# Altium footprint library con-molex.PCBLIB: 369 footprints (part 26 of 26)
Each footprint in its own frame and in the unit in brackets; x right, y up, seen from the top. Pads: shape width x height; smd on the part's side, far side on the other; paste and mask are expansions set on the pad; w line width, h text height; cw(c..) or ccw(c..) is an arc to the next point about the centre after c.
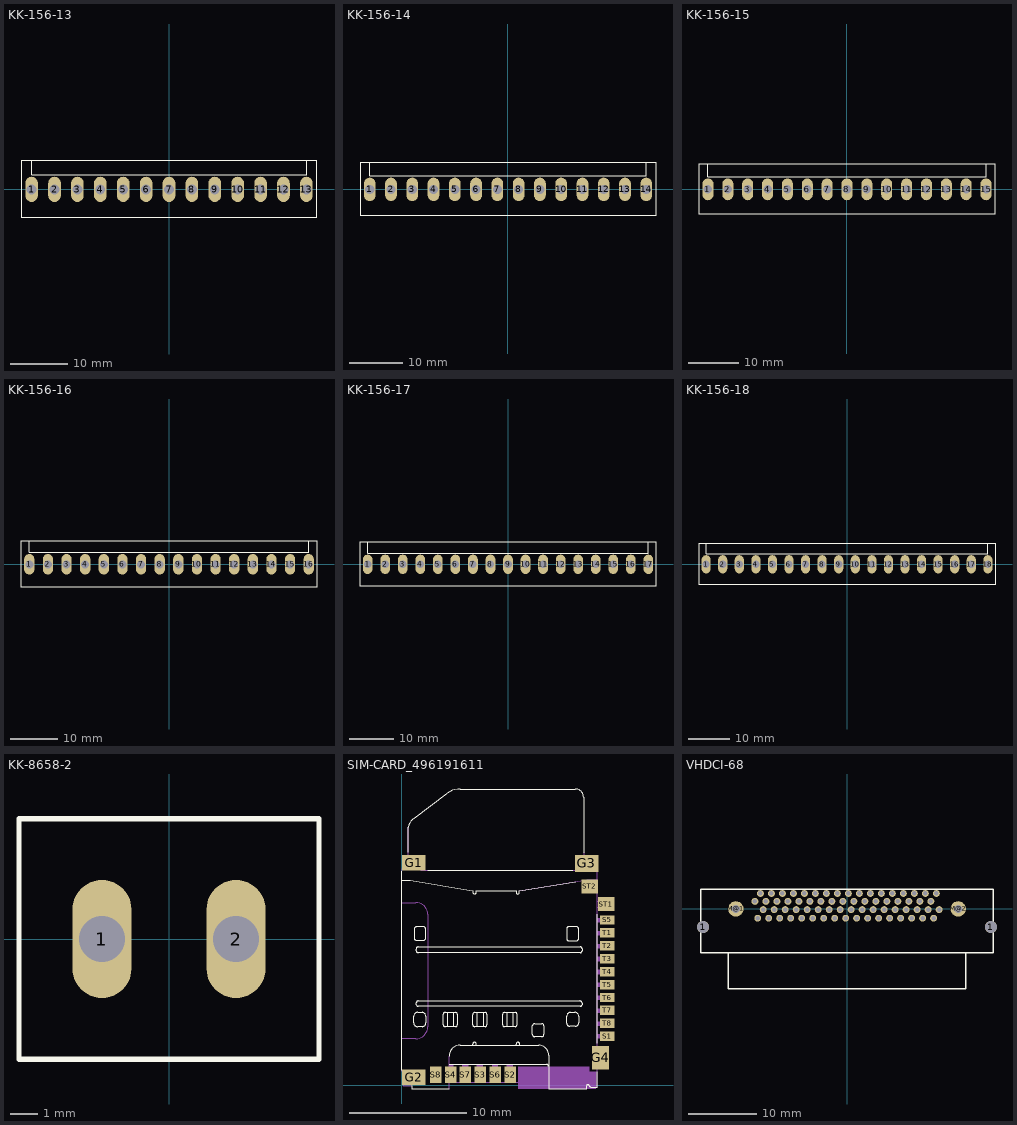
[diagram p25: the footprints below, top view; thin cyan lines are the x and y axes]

## KK-156-13 [mil]
pads (13):
  oval 86x172 hole 66.93: 1(-935.43,0) 2(-779.53,0) 3(-623.62,0) 4(-467.72,0) 5(-311.81,0) 6(-155.91,0) 7(0,0) 8(155.91,0) 9(311.81,0) 10(467.72,0) 11(623.62,0) 12(779.53,0) 13(935.43,0)
Top Overlay:
  lines w8: -935.63,194.88 936.61,194.88 ; -935.63,194.88 -1006.5,194.88 -1006.5,-189.96 1007.48,-189.96 1007.48,194.88 936.61,194.88 ; -935.63,194.88 -935.63,99.41 936.61,99.41 936.61,194.88

## KK-156-14 [mil]
pads (14):
  oval 86x172 hole 66.93: 1(-1013.39,0) 2(-857.48,0) 3(-701.57,0) 4(-545.67,0) 5(-389.76,0) 6(-233.86,0) 7(-77.95,0) 8(77.95,0) 9(233.86,0) 10(389.76,0) 11(545.67,0) 12(701.57,0) 13(857.48,0) 14(1013.39,0)
Top Overlay:
  lines w8: -1013.58,194.88 1014.57,194.88 ; -1013.58,194.88 -1084.45,194.88 -1084.45,-189.96 1085.43,-189.96 1085.43,194.88 1014.57,194.88 ; -1013.58,194.88 -1013.58,99.41 1014.57,99.41 1014.57,194.88

## KK-156-15 [mil]
pads (15):
  oval 86x172 hole 66.93: 1(-1091.34,0) 2(-935.43,0) 3(-779.53,0) 4(-623.62,0) 5(-467.72,0) 6(-311.81,0) 7(-155.91,0) 8(0,0) 9(155.91,0) 10(311.81,0) 11(467.72,0) 12(623.62,0) 13(779.53,0) 14(935.43,0) 15(1091.34,0)
Top Overlay:
  lines w8: -1091.54,194.88 1092.52,194.88 ; -1091.54,194.88 -1162.4,194.88 -1162.4,-189.96 1163.39,-189.96 1163.39,194.88 1092.52,194.88 ; -1091.54,194.88 -1091.54,99.41 1092.52,99.41 1092.52,194.88

## KK-156-16 [mil]
pads (16):
  oval 86x172 hole 66.93: 1(-1169.29,0) 2(-1013.39,0) 3(-857.48,0) 4(-701.57,0) 5(-545.67,0) 6(-389.76,0) 7(-233.86,0) 8(-77.95,0) 9(77.95,0) 10(233.86,0) 11(389.76,0) 12(545.67,0) 13(701.57,0) 14(857.48,0) 15(1013.39,0) 16(1169.29,0)
Top Overlay:
  lines w8: -1169.49,194.88 1170.47,194.88 ; -1169.49,194.88 -1240.35,194.88 -1240.35,-189.96 1241.34,-189.96 1241.34,194.88 1170.47,194.88 ; -1169.49,194.88 -1169.49,99.41 1170.47,99.41 1170.47,194.88

## KK-156-17 [mil]
pads (17):
  oval 86x172 hole 66.93: 1(-1247.24,0) 2(-1091.34,0) 3(-935.43,0) 4(-779.53,0) 5(-623.62,0) 6(-467.72,0) 7(-311.81,0) 8(-155.91,0) 9(0,0) 10(155.91,0) 11(311.81,0) 12(467.72,0) 13(623.62,0) 14(779.53,0) 15(935.43,0) 16(1091.34,0) 17(1247.24,0)
Top Overlay:
  lines w8: -1247.44,194.88 1248.43,194.88 ; -1247.44,194.88 -1318.31,194.88 -1318.31,-189.96 1319.29,-189.96 1319.29,194.88 1248.43,194.88 ; -1247.44,194.88 -1247.44,99.41 1248.43,99.41 1248.43,194.88

## KK-156-18 [mil]
pads (18):
  oval 86x172 hole 66.93: 1(-1325.2,0) 2(-1169.29,0) 3(-1013.39,0) 4(-857.48,0) 5(-701.57,0) 6(-545.67,0) 7(-389.76,0) 8(-233.86,0) 9(-77.95,0) 10(77.95,0) 11(233.86,0) 12(389.76,0) 13(545.67,0) 14(701.57,0) 15(857.48,0) 16(1013.39,0) 17(1169.29,0) 18(1325.2,0)
Top Overlay:
  lines w8: -1325.39,194.88 1326.38,194.88 ; -1325.39,194.88 -1396.26,194.88 -1396.26,-189.96 1397.24,-189.96 1397.24,194.88 1326.38,194.88 ; -1325.39,194.88 -1325.39,99.41 1326.38,99.41 1326.38,194.88

## KK-8658-2 [mil]
pads (2):
  oval 86x172 hole 66.93: 1(-97.64,0) 2(97.64,0)
Top Overlay:
  lines w7.99: -218.5,175 218.5,175
  lines w8: -218.5,175 -218.5,-175 218.5,-175 218.5,175

## SIM-CARD_496191611 [mm]
pads (22):
  rect 2x1.35 smd: G1(1,18.937) G2(1,0.675)
  rect 2x1.45 smd: G3(15.75,18.887)
  rect 1.45x2 smd: G4(16.925,2.35)
  rect 1.25x0.8 smd: S1(17.475,4.163) S5(17.475,14.062) T1(17.475,12.962) T2(17.475,11.863) T3(17.475,10.762) T4(17.475,9.662) T5(17.475,8.563) T6(17.475,7.463) T7(17.475,6.362) T8(17.475,5.263)
  rect 0.98x1.4 smd: S2(9.225,0.9) S3(6.685,0.9) S4(4.145,0.9) S6(7.955,0.9) S7(5.415,0.9) S8(2.875,0.9)
  rect 1.4x1.2 smd: ST1(17.4,15.412) ST2(16,16.913)
Top Overlay:
  lines w0.05: -0.032,1.27 -0.032,18.226 ; 0,17.464 0.73,17.464 6.033,16.543 6.033,16.448 ccw(c6.192,16.448) 6.351,16.448 6.351,16.543 9.717,16.543 9.717,16.416 ccw(c9.859,16.416) 10.002,16.416 10.002,16.543 14.797,17.337 ; 0.54,19.846 0.54,21.973 ; 0.857,-0.064 0.857,-0.318 4.033,-0.318 ; 2.223,18.29 14.543,18.29 ; 4.033,2.477 cw(c4.953,2.477) 4.954,3.398 11.653,3.398 cw(c11.653,2.54) 12.511,2.54 12.511,0.254 12.511,-0.318 15.718,-0.318 15.718,-0.095 15.718,-0.064 cw(c15.831,-0.064) 15.94,-0.032 ccw(c16.111,0.018) 16.131,-0.159 16.639,-0.159 16.639,1.143 ; 6.033,3.398 6.033,3.493 cw(c6.192,3.493) 6.192,3.652 cw(c6.192,3.493) 6.351,3.493 6.351,3.398 ; 9.717,3.398 9.717,3.493 cw(c9.875,3.493) 9.875,3.652 cw(c9.875,3.493) 10.034,3.493 10.034,3.398 ; 15.464,19.782 15.464,24.512 ccw(c14.764,24.512) 14.764,25.212 4.985,25.212 ccw(c4.967,23.326) 3.874,24.863 1.048,22.703 ccw(c1.64,21.749) 0.54,21.973 ; 16.639,3.556 16.639,14.543 ; 0.54,21.973 0.54,21.973 ; 1.048,12.543 ccw(c1.27,12.543) 1.27,12.32 1.81,12.32 ccw(c1.81,12.543) 2.032,12.543 2.032,13.273 ccw(c1.81,13.273) 1.81,13.495 1.27,13.495 ccw(c1.286,13.257) 1.048,13.241 1.048,12.543 ; 1.207,11.463 ccw(c1.397,11.463) 1.397,11.272 7.621,11.272 9.304,11.272 12.13,11.272 14.638,11.272 15.178,11.272 ccw(c15.178,11.431) 15.337,11.431 15.337,11.622 ccw(c15.178,11.622) 15.178,11.78 1.397,11.78 ccw(c1.397,11.59) 1.207,11.59 1.206,11.463 ; 14.035,12.479 14.035,12.511 14.035,13.305 cw(c14.225,13.305) 14.225,13.495 14.829,13.495 cw(c14.829,13.273) 15.051,13.273 15.051,12.511 cw(c14.829,12.511) 14.829,12.289 14.225,12.289 cw(c14.225,12.479) 14.035,12.479
  lines w0.1: 3.842,5.049 3.842,6.16 ; 4.033,1.778 12.32,1.778 cw(c12.32,1.62) 12.479,1.62 ; 4.382,5.017 4.382,6.16 ; 6.382,5.049 6.382,6.16 ; 6.922,5.049 6.922,6.16 ; 8.923,5.049 8.923,6.16 ; 9.431,5.017 9.431,6.16 ; 16.924,15.21 16.924,15.242 ; 1.016,5.303 ccw(c1.333,5.303) 1.333,4.985 1.715,4.985 ccw(c1.715,5.303) 2.032,5.303 2.032,5.874 ccw(c1.715,5.874) 1.715,6.192 1.333,6.192 ccw(c1.333,5.874) 1.016,5.874 1.016,5.303 ; 1.238,6.859 ccw(c1.397,6.859) 1.397,6.7 4.033,6.7 15.051,6.7 15.178,6.7 ccw(c15.178,6.859) 15.337,6.859 15.337,6.986 ccw(c15.146,6.986) 15.146,7.176 1.556,7.176 1.397,7.176 ccw(c1.397,7.017) 1.238,7.018 1.238,6.859 ; 3.525,5.144 ccw(c3.683,5.144) 3.683,4.985 4.573,4.985 ccw(c4.573,5.144) 4.731,5.144 4.731,6.033 ccw(c4.573,6.033) 4.573,6.192 3.683,6.192 ccw(c3.683,6.033) 3.525,6.033 3.525,5.144 ; 6.033,5.144 ccw(c6.192,5.144) 6.192,4.985 7.081,4.985 ccw(c7.081,5.144) 7.24,5.144 7.24,6.033 ccw(c7.081,6.033) 7.081,6.192 6.255,6.192 6.224,6.192 ccw(c6.224,6.001) 6.033,6.001 6.033,5.144 ; 8.573,5.144 ccw(c8.732,5.144) 8.732,4.985 9.653,4.985 ccw(c9.653,5.112) 9.78,5.112 9.78,6.097 ccw(c9.685,6.097) 9.685,6.192 8.732,6.192 ccw(c8.732,6.033) 8.573,6.033 8.573,5.144 ; 11.114,4.319 ccw(c11.304,4.319) 11.304,4.128 11.907,4.128 ccw(c11.907,4.319) 12.098,4.319 12.098,5.049 ccw(c11.907,5.049) 11.907,5.239 11.399,5.239 11.304,5.239 ccw(c11.304,5.049) 11.114,5.049 11.114,4.319 ; 14.035,5.271 ccw(c14.289,5.271) 14.289,5.017 14.765,5.017 ccw(c14.765,5.303) 15.051,5.303 15.051,5.874 ccw(c14.733,5.874) 14.733,6.192 14.352,6.192 ccw(c14.352,5.874) 14.035,5.874 14.035,5.271
Mechanical 16:
  rectangle: 16.639,13.844 17.687,14.225
  rectangle: 16.67,12.733 17.687,13.114
  rectangle: 16.67,11.622 17.687,12.034
  rectangle: 16.67,10.542 17.687,10.955
  rectangle: 16.67,9.431 17.687,9.844
  rectangle: 16.67,8.351 17.687,8.732
  rectangle: 16.67,7.272 17.687,7.653
  rectangle: 16.639,6.16 17.687,6.541
  rectangle: 16.67,5.049 17.687,5.43
  rectangle: 16.639,3.969 17.687,4.35
  rectangle: 4.001,0.667 4.382,1.747
  rectangle: 5.112,0.667 5.652,1.747
  rectangle: 6.351,0.667 6.922,1.715
  rectangle: 7.653,0.667 8.192,1.747
  rectangle: 8.891,0.699 9.463,1.747
  lines w0.05: -0.032,1.27 ccw(c0.162,1.27) 0.127,1.079 0.127,-0.064 0.857,-0.064 ; -0.032,18.226 cw(c0.286,18.226) 0.286,18.544 0.286,18.957 cw(c0.445,18.957) 0.445,19.115 0.667,19.115 cw(c0.667,18.957) 0.826,18.957 0.826,18.925 ccw(c0.921,18.925) 0.921,18.83 ccw(c0.921,18.925) 1.016,18.925 cw(c1.206,18.925) 1.206,19.115 1.429,19.115 cw(c1.429,18.957) 1.588,18.957 1.588,18.29 15.051,18.29 15.051,18.861 15.051,18.988 cw(c15.178,18.988) 15.178,19.115 15.432,19.115 cw(c15.432,18.988) 15.559,18.988 15.559,18.957 15.559,18.925 ccw(c15.686,18.925) 15.686,18.798 ccw(c15.686,18.925) 15.813,18.925 15.813,18.988 cw(c15.94,18.988) 15.94,19.115 16.194,19.115 cw(c16.194,18.957) 16.353,18.957 16.353,18.512 cw(c16.353,18.226) 16.639,18.226 16.639,18.195 16.639,1.683 16.639,-0.159 ; 0.54,19.147 0.54,21.973 ; 4.033,-0.318 4.033,0.254 ; 4.033,2.477 4.033,0.254 ; 10.002,16.543 15.75,17.496 16.607,17.496 ; 12.511,0.254 4.033,0.254 ; 15.464,19.147 15.464,19.781
  lines w0.1: 0,15.55 1.2,15.55 cw(c1.2,14.55) 2.2,14.55 2.2,4.962 cw(c1.187,4.962) 1.187,3.95 0.006,3.95 ; 16.67,1.747 16.988,1.747 ccw(c16.988,1.937) 17.178,1.937 17.178,2.064 ccw(c17.02,2.064) 17.02,2.223 16.988,2.223 cw(c16.988,2.35) 16.861,2.35 16.861,2.382 cw(c16.988,2.382) 16.988,2.509 17.051,2.509 ccw(c17.051,2.636) 17.178,2.636 17.178,2.731 ccw(c16.988,2.76) 16.988,2.953 16.67,2.953 ; 16.67,15.083 16.797,15.083 ccw(c16.797,15.21) 16.924,15.21 ; 16.67,15.654 16.734,15.654 16.797,15.654 cw(c16.797,15.527) 16.924,15.527 16.924,15.242
Mechanical 27:
  rectangle: 9.9,-0.325 15.988,1.6
  rectangle: 15.988,-0.325 16.537,1.175

## VHDCI-68 [mm]
pads (72):
  round 1.75 hole 1.75: 1(-20.95,-2.63) 1(20.95,-2.63)
  round 1 hole 0.65: 1(13.005,2.25) 2(12.205,1.1) 3(11.405,2.25) 4(10.605,1.1) 5(9.805,2.25) 6(9.005,1.1) 7(8.205,2.25) 8(7.405,1.1) 9(6.605,2.25) 10(5.805,1.1) 11(5.005,2.25) 12(4.205,1.1) 13(3.405,2.25) 14(2.605,1.1) 15(1.805,2.25) 16(1.005,1.1) 17(0.205,2.25) 18(-0.595,1.1) 19(-1.395,2.25) 20(-2.195,1.1) 21(-2.995,2.25) 22(-3.795,1.1) 23(-4.595,2.25) 24(-5.395,1.1) 25(-6.195,2.25) 26(-6.995,1.1) 27(-7.795,2.25) 28(-8.595,1.1) 29(-9.395,2.25) 30(-10.195,1.1) 31(-10.995,2.25) 32(-11.795,1.1) 33(-12.595,2.25) 34(-13.395,1.1) 35(13.405,-0.1) 36(12.605,-1.35) 37(11.805,-0.1) 38(11.005,-1.35) 39(10.205,-0.1) 40(9.405,-1.35) 41(8.605,-0.1) 42(7.805,-1.35) 43(7.005,-0.1) 44(6.205,-1.35) 45(5.405,-0.1) 46(4.605,-1.35) 47(3.805,-0.1) 48(3.005,-1.35) 49(2.205,-0.1) 50(1.405,-1.35) 51(0.605,-0.1) 52(-0.195,-1.35) 53(-0.995,-0.1) 54(-1.795,-1.35) 55(-2.595,-0.1) 56(-3.395,-1.35) 57(-4.195,-0.1) 58(-4.995,-1.35) 59(-5.795,-0.1) 60(-6.595,-1.35) 61(-7.395,-0.1) 62(-8.195,-1.35) 63(-8.995,-0.1) 64(-9.795,-1.35) 65(-10.595,-0.1) 66(-11.395,-1.35) 67(-12.195,-0.1) 68(-12.995,-1.35)
  round 2.25 hole 1.2: M@1(-16.175,0) M@2(16.175,0)
Top Overlay:
  lines w0.203: -17.25,-6.4 -17.25,-11.6 17.25,-11.6 17.25,-6.4 ; -17.25,-6.4 -21.25,-6.4 -21.25,2.85 21.263,2.85 21.263,-6.4 17.25,-6.4 ; -17.25,-6.4 17.25,-6.4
